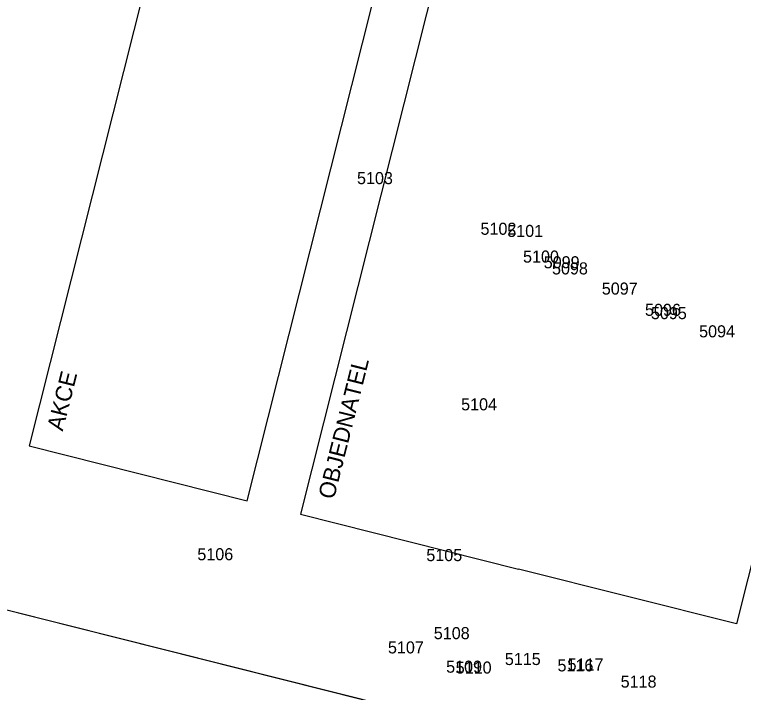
# Model space of a CAD drawing. Extents: x -740053 to -737517, y -1033516 to -1032488.
# Drawn here: x -738977.72 to -738944.49, y -1033022.69 to -1032991.77 of the extents above; entities that cross this region are included whole.
import ezdxf

# ---------------------------------------------------------------- set-up
doc = ezdxf.new("R2010")
doc.units = 0
for name, color, linetype in [('bod-cislo', 7, 'Continuous'), ('Predmety bez rozlišeni', 7, 'Continuous'), ('promika-formát', 7, 'Continuous'), ('promika-rozp', 7, 'Continuous')]:
    doc.layers.add(name, color=color, linetype=linetype)

msp = doc.modelspace()

# ---------------------------------------------------------------- linework, layer by layer
at = {"layer": 'Predmety bez rozlišeni'}
msp.add_line((-739035.13, -1033004.562), (-738891.123, -1033040.815), dxfattribs=at)
at = {"layer": 'promika-formát'}
msp.add_lwpolyline([(-738891.123, -1033040.815), (-738865.49, -1032938.992), (-739009.497, -1032902.739), (-739035.13, -1033004.562)], close=True, dxfattribs=at)
at = {"layer": 'promika-rozp'}
msp.add_lwpolyline([(-738967.114, -1033013.951), (-738945.143, -1032926.674), (-738955.083, -1032924.172), (-738977.054, -1033011.449)], close=True, dxfattribs=at)
for points in [[(-738932.779, -1032929.787), (-738942.719, -1032927.284), (-738964.69, -1033014.561), (-738954.75, -1033017.063)], [(-738932.779, -1032929.787), (-738922.839, -1032932.289), (-738944.81, -1033019.566), (-738954.75, -1033017.063)]]:
    msp.add_lwpolyline(points, dxfattribs=at)

# ---------------------------------------------------------------- texts
at = {"layer": 'bod-cislo'}
for s, p in [('5103', (-738962.108, -1032999.503)), ('5102', (-738956.478, -1033001.813)), ('5101', (-738955.259, -1033001.913)), ('5100', (-738954.538, -1033003.083)), ('5099', (-738953.595, -1033003.343)), ('5098', (-738953.218, -1033003.623)), ('5097', (-738950.948, -1033004.543)), ('5096', (-738948.978, -1033005.513)), ('5095', (-738948.708, -1033005.663)), ('5094', (-738946.511, -1033006.493)), ('5104', (-738957.361, -1033009.823)), ('5106', (-738969.388, -1033016.663)), ('5105', (-738958.948, -1033016.703)), ('5108', (-738958.608, -1033020.263)), ('5107', (-738960.698, -1033020.913)), ('5115', (-738955.368, -1033021.443)), ('5109', (-738958.045, -1033021.793)), ('5110', (-738957.608, -1033021.833)), ('5116', (-738952.968, -1033021.733)), ('5117', (-738952.508, -1033021.693)), ('5118', (-738950.088, -1033022.473))]:
    msp.add_text(s, height=0.55, dxfattribs=at).set_placement(p)
at = {"layer": 'promika-rozp'}
for s, p in [('OBJEDNATEL', (-738963.161, -1033013.917)), ('AKCE', (-738975.525, -1033010.804))]:
    msp.add_text(s, height=0.75, rotation=75.8698, dxfattribs=at).set_placement(p)

doc.saveas('drawing.dxf')
